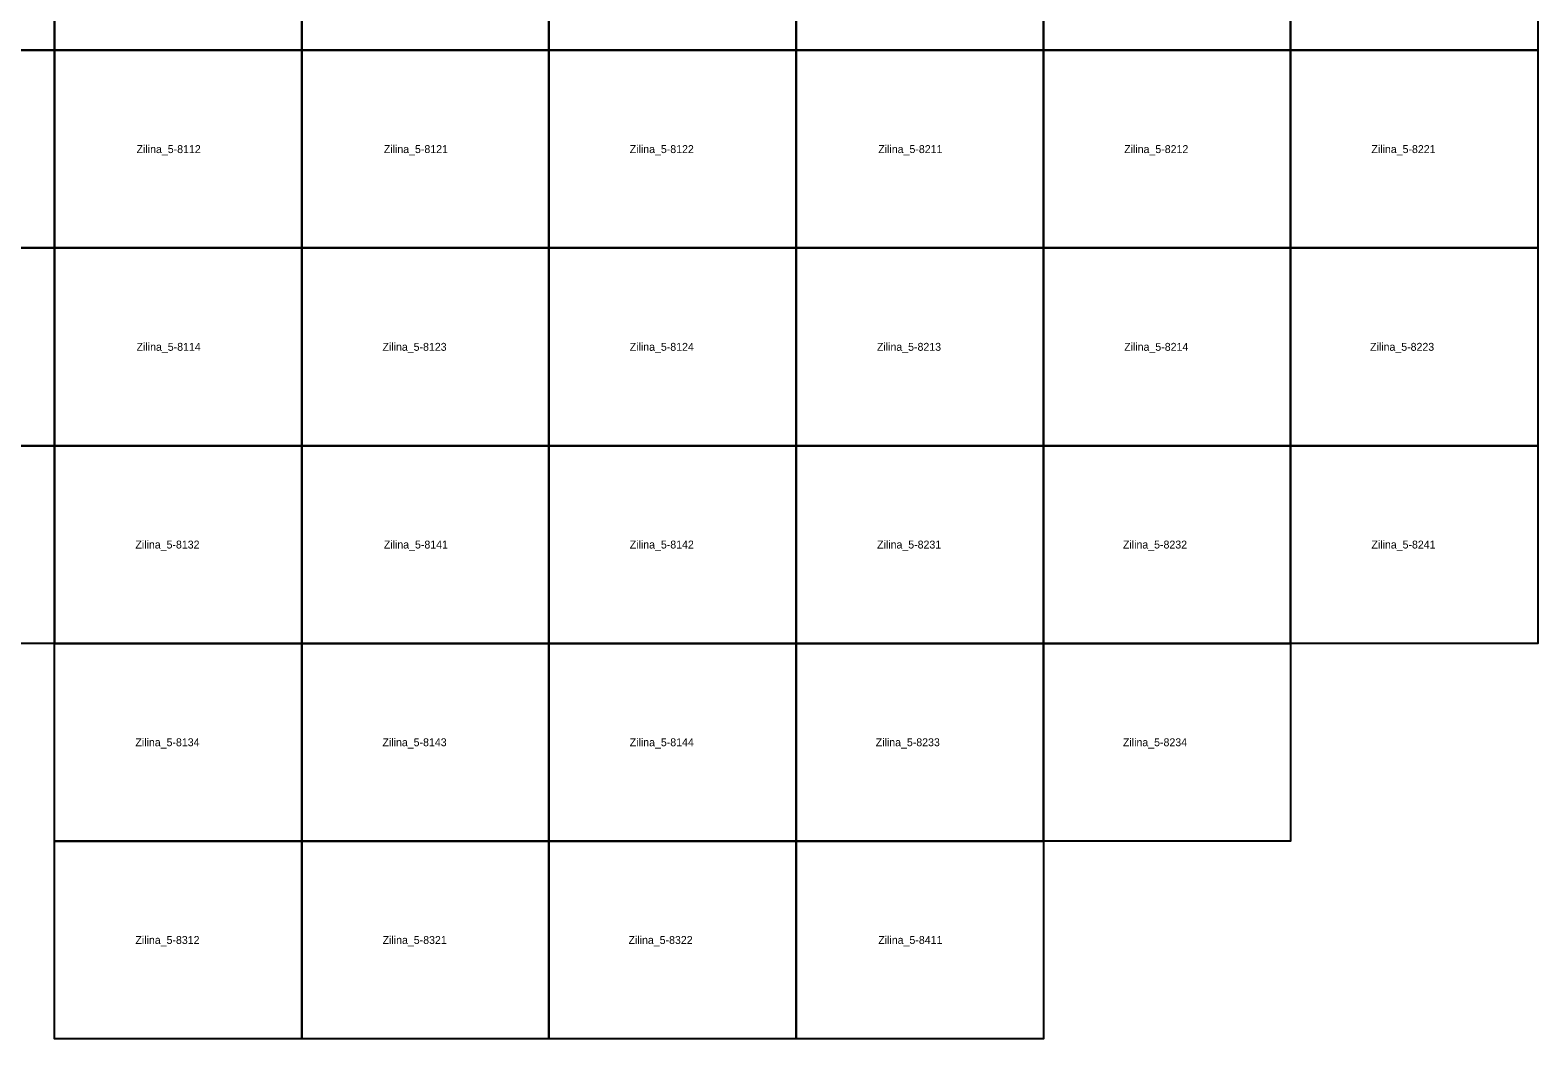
# Model space of a CAD drawing. Extents: x -445938 to -437812, y -1177250 to -1169500.
# Drawn here: x -439718 to -437812, y -1177250 to -1175975 of the extents above; entities that cross this region are included whole.
import ezdxf

# ---------------------------------------------------------------- set-up
doc = ezdxf.new("R2010")
doc.units = 0
for name, color, linetype in [('Vrstva 1', 7, 'Continuous'), ('Vrstva 4', 7, 'Continuous'), ('Vrstva 6', 7, 'Continuous')]:
    doc.layers.add(name, color=color, linetype=linetype)

msp = doc.modelspace()

# ---------------------------------------------------------------- linework, layer by layer
at = {"layer": 'Vrstva 1'}
msp.add_lwpolyline([(-440937.5, -1172000), (-440625, -1172000), (-440625, -1173000), (-440000, -1173000), (-440000, -1173500), (-439375, -1173500), (-439375, -1173750), (-438750, -1173750), (-438750, -1174000), (-438125, -1174000), (-438125, -1174750), (-437812.5, -1174750), (-437812.5, -1176750), (-438125, -1176750), (-438125, -1177000), (-438437.5, -1177000), (-438437.5, -1177250), (-439687.5, -1177250), (-439687.5, -1176750), (-440625, -1176750), (-440625, -1175500), (-441562.5, -1175500)], dxfattribs=at)
at = {"layer": 'Vrstva 4'}
for points in [[(-439687.5, -1175750), (-439687.5, -1176000), (-440000, -1176000), (-440000, -1175750)], [(-439375, -1175750), (-439375, -1176000), (-439687.5, -1176000), (-439687.5, -1175750)], [(-439062.5, -1175750), (-439062.5, -1176000), (-439375, -1176000), (-439375, -1175750)], [(-438750, -1175750), (-438750, -1176000), (-439062.5, -1176000), (-439062.5, -1175750)], [(-438437.5, -1175750), (-438437.5, -1176000), (-438750, -1176000), (-438750, -1175750)], [(-438125, -1175750), (-438125, -1176000), (-438437.5, -1176000), (-438437.5, -1175750)], [(-437812.5, -1175750), (-437812.5, -1176000), (-438125, -1176000), (-438125, -1175750)], [(-439687.5, -1176000), (-439687.5, -1176250), (-440000, -1176250), (-440000, -1176000)], [(-439375, -1176000), (-439375, -1176250), (-439687.5, -1176250), (-439687.5, -1176000)], [(-439062.5, -1176000), (-439062.5, -1176250), (-439375, -1176250), (-439375, -1176000)], [(-438750, -1176000), (-438750, -1176250), (-439062.5, -1176250), (-439062.5, -1176000)], [(-438437.5, -1176000), (-438437.5, -1176250), (-438750, -1176250), (-438750, -1176000)], [(-438125, -1176000), (-438125, -1176250), (-438437.5, -1176250), (-438437.5, -1176000)], [(-437812.5, -1176000), (-437812.5, -1176250), (-438125, -1176250), (-438125, -1176000)], [(-439687.5, -1176250), (-439687.5, -1176500), (-440000, -1176500), (-440000, -1176250)], [(-439375, -1176250), (-439375, -1176500), (-439687.5, -1176500), (-439687.5, -1176250)], [(-439062.5, -1176250), (-439062.5, -1176500), (-439375, -1176500), (-439375, -1176250)], [(-438750, -1176250), (-438750, -1176500), (-439062.5, -1176500), (-439062.5, -1176250)], [(-438437.5, -1176250), (-438437.5, -1176500), (-438750, -1176500), (-438750, -1176250)], [(-438125, -1176250), (-438125, -1176500), (-438437.5, -1176500), (-438437.5, -1176250)], [(-437812.5, -1176250), (-437812.5, -1176500), (-438125, -1176500), (-438125, -1176250)], [(-439687.5, -1176500), (-439687.5, -1176750), (-440000, -1176750), (-440000, -1176500)], [(-439375, -1176500), (-439375, -1176750), (-439687.5, -1176750), (-439687.5, -1176500)], [(-439062.5, -1176500), (-439062.5, -1176750), (-439375, -1176750), (-439375, -1176500)], [(-438750, -1176500), (-438750, -1176750), (-439062.5, -1176750), (-439062.5, -1176500)], [(-438437.5, -1176500), (-438437.5, -1176750), (-438750, -1176750), (-438750, -1176500)], [(-438125, -1176500), (-438125, -1176750), (-438437.5, -1176750), (-438437.5, -1176500)], [(-437812.5, -1176500), (-437812.5, -1176750), (-438125, -1176750), (-438125, -1176500)], [(-439375, -1176750), (-439375, -1177000), (-439687.5, -1177000), (-439687.5, -1176750)], [(-439062.5, -1176750), (-439062.5, -1177000), (-439375, -1177000), (-439375, -1176750)], [(-438750, -1176750), (-438750, -1177000), (-439062.5, -1177000), (-439062.5, -1176750)], [(-438437.5, -1176750), (-438437.5, -1177000), (-438750, -1177000), (-438750, -1176750)], [(-438125, -1176750), (-438125, -1177000), (-438437.5, -1177000), (-438437.5, -1176750)], [(-439375, -1177000), (-439375, -1177250), (-439687.5, -1177250), (-439687.5, -1177000)], [(-439062.5, -1177000), (-439062.5, -1177250), (-439375, -1177250), (-439375, -1177000)], [(-438750, -1177000), (-438750, -1177250), (-439062.5, -1177250), (-439062.5, -1177000)], [(-438437.5, -1177000), (-438437.5, -1177250), (-438750, -1177250), (-438750, -1177000)]]:
    msp.add_lwpolyline(points, close=True, dxfattribs=at)

# ---------------------------------------------------------------- texts
at = {"layer": 'Vrstva 6'}
for s, p in [('Zilina_5-8112', (-439583.686, -1176130)), ('Zilina_5-8121', (-439271.186, -1176130)), ('Zilina_5-8122', (-438960.379, -1176130)), ('Zilina_5-8211', (-438646.186, -1176130)), ('Zilina_5-8212', (-438335.379, -1176130)), ('Zilina_5-8221', (-438022.878, -1176130)), ('Zilina_5-8114', (-439583.686, -1176380)), ('Zilina_5-8123', (-439272.879, -1176380)), ('Zilina_5-8124', (-438960.379, -1176380)), ('Zilina_5-8213', (-438647.879, -1176380)), ('Zilina_5-8214', (-438335.379, -1176380)), ('Zilina_5-8223', (-438024.572, -1176380)), ('Zilina_5-8132', (-439585.222, -1176630)), ('Zilina_5-8141', (-439271.186, -1176630)), ('Zilina_5-8142', (-438960.379, -1176630)), ('Zilina_5-8231', (-438647.721, -1176630)), ('Zilina_5-8232', (-438336.914, -1176630)), ('Zilina_5-8241', (-438022.878, -1176630)), ('Zilina_5-8134', (-439585.222, -1176880)), ('Zilina_5-8143', (-439272.879, -1176880)), ('Zilina_5-8144', (-438960.379, -1176880)), ('Zilina_5-8233', (-438649.414, -1176880)), ('Zilina_5-8234', (-438336.914, -1176880)), ('Zilina_5-8312', (-439585.222, -1177130)), ('Zilina_5-8321', (-439272.721, -1177130)), ('Zilina_5-8322', (-438961.914, -1177130)), ('Zilina_5-8411', (-438646.186, -1177130))]:
    msp.add_text(s, height=10, dxfattribs=at).set_placement(p)

doc.saveas('drawing.dxf')
